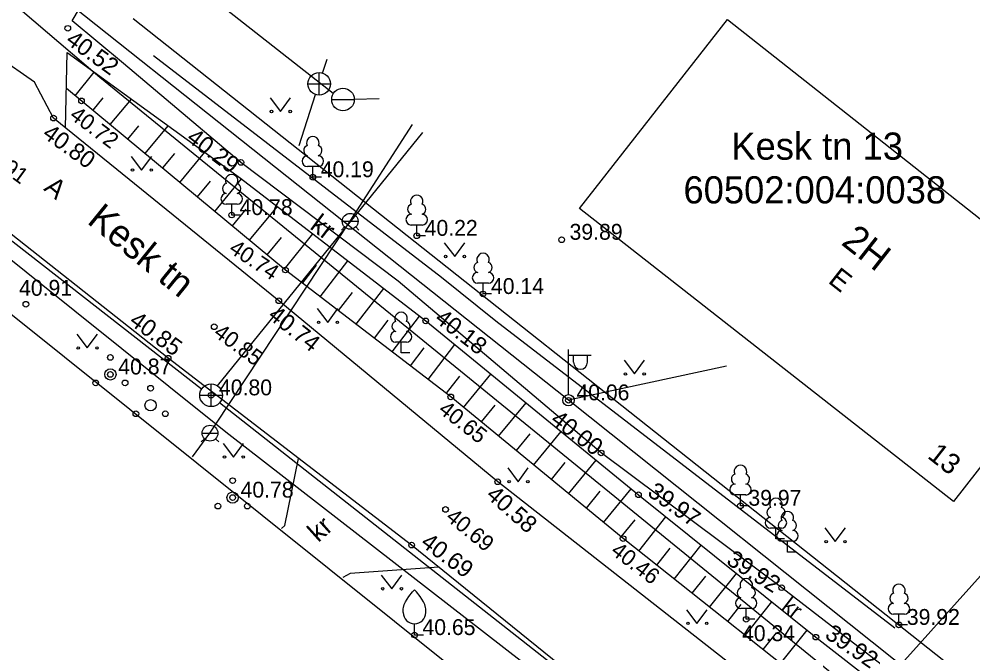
# Model space of a CAD drawing. Extents: x 641898 to 642452, y 6471715 to 6472255.
# Drawn here: x 642247.36 to 642289.49, y 6471869.14 to 6471897.14 of the extents above; entities that cross this region are included whole.
import ezdxf

# ---------------------------------------------------------------- set-up
doc = ezdxf.new("R2010")
doc.units = 0
for name, color, linetype in [('HALJASTUS', 7, 'Continuous'), ('HOONE', 7, 'Continuous'), ('KKAEV', 7, 'Continuous'), ('KORGUS-EH2000', 7, 'Continuous'), ('KTRASS', 7, 'Continuous'), ('MPOHULIIN', 7, 'Continuous'), ('PIIR', 7, 'Continuous'), ('POST', 7, 'Continuous'), ('PUU', 7, 'Continuous'), ('RELJEEF', 7, 'Continuous'), ('TEE', 7, 'Continuous'), ('VKAEV', 7, 'Continuous'), ('VTRASS', 7, 'Continuous')]:
    doc.layers.add(name, color=color, linetype=linetype)

msp = doc.modelspace()

# ---------------------------------------------------------------- linework, layer by layer
at = {"layer": 'HALJASTUS'}
for p, q in [((642258.446, 6471893.663), (642258.91, 6471893.056)), ((642258.91, 6471893.056), (642259.355, 6471893.663)), ((642252.309, 6471891.077), (642252.772, 6471890.47)), ((642252.772, 6471890.47), (642253.218, 6471891.077)), ((642266.14, 6471887.258), (642266.603, 6471886.651)), ((642266.603, 6471886.651), (642267.049, 6471887.258)), ((642260.531, 6471884.349), (642260.994, 6471883.742)), ((642260.994, 6471883.742), (642261.44, 6471884.349)), ((642249.91, 6471883.22), (642250.373, 6471882.613)), ((642250.373, 6471882.613), (642250.819, 6471883.22)), ((642274.083, 6471882.072), (642274.546, 6471881.465)), ((642274.546, 6471881.465), (642274.992, 6471882.072)), ((642256.37, 6471878.401), (642256.834, 6471877.794)), ((642256.834, 6471877.794), (642257.279, 6471878.401)), ((642268.944, 6471877.312), (642269.407, 6471876.705)), ((642269.407, 6471876.705), (642269.853, 6471877.312)), ((642282.951, 6471874.667), (642283.414, 6471874.061)), ((642283.414, 6471874.061), (642283.86, 6471874.667)), ((642263.359, 6471872.583), (642263.822, 6471871.977)), ((642263.822, 6471871.977), (642264.268, 6471872.583)), ((642276.843, 6471871.053), (642277.306, 6471870.447)), ((642277.306, 6471870.447), (642277.752, 6471871.053))]:
    msp.add_line(p, q, dxfattribs=at)
msp.add_lwpolyline([(642253.304, 6471895.534), (642266.025, 6471885.741), (642268.417, 6471883.816), (642286.045, 6471870.255)], dxfattribs=at)
for centre in [(642258.509, 6471893.056), (642259.337, 6471893.056), (642252.371, 6471890.47), (642253.2, 6471890.47), (642266.202, 6471886.651), (642267.031, 6471886.651), (642260.593, 6471883.742), (642261.422, 6471883.742), (642249.972, 6471882.613), (642250.801, 6471882.613), (642274.145, 6471881.465), (642274.974, 6471881.465), (642256.433, 6471877.794), (642257.261, 6471877.794), (642269.006, 6471876.705), (642269.835, 6471876.705), (642283.013, 6471874.061), (642283.842, 6471874.061), (642263.421, 6471871.977), (642264.25, 6471871.977), (642276.905, 6471870.447), (642277.734, 6471870.447)]:
    msp.add_circle(centre, 0.055, dxfattribs=at)
at = {"layer": 'HOONE'}
msp.add_lwpolyline([(642295.123, 6471884.142), (642288.643, 6471875.825), (642272.118, 6471888.773), (642278.654, 6471897.128), (642295.123, 6471884.142)], dxfattribs=at)
at = {"layer": 'KKAEV'}
for p, q in [((642260.614, 6471893.779), (642260.614, 6471894.779)), ((642260.114, 6471894.279), (642261.114, 6471894.279)), ((642255.841, 6471880.022), (642255.841, 6471881.022)), ((642255.341, 6471880.522), (642256.341, 6471880.522))]:
    msp.add_line(p, q, dxfattribs=at)
for centre in [(642260.614, 6471894.279), (642255.841, 6471880.522)]:
    msp.add_circle(centre, 0.5, dxfattribs=at)
at = {"layer": 'KORGUS-EH2000'}
for centre in [(642249.511, 6471896.733), (642250.117, 6471893.526), (642248.882, 6471892.766), (642257.161, 6471890.808), (642260.336, 6471890.156), (642256.752, 6471888.484), (642264.926, 6471887.567), (642271.328, 6471887.393), (642259.128, 6471886.055), (642267.855, 6471884.997), (642258.832, 6471884.697), (642255.978, 6471883.551), (642265.322, 6471883.81), (642253.944, 6471882.162), (642251.393, 6471881.444), (642255.841, 6471880.522), (642266.428, 6471880.453), (642271.629, 6471880.301), (642273.071, 6471877.975), (642268.501, 6471876.701), (642256.794, 6471876.004), (642274.72, 6471876.131), (642266.199, 6471875.479), (642279.226, 6471875.645), (642274.043, 6471874.191), (642264.701, 6471873.908), (642281.048, 6471872.025), (642279.481, 6471870.628), (642286.226, 6471870.383), (642264.829, 6471869.934), (642282.556, 6471869.84)]:
    msp.add_circle(centre, 0.125, dxfattribs=at)
at = {"layer": 'KTRASS'}
for points in [[(642255.424, 6471880.798), (642227.22, 6471902.81)], [(642260.769, 6471894.754), (642260.971, 6471895.375)], [(642259.734, 6471891.562), (642260.46, 6471893.803)], [(642265.186, 6471892.134), (642256.105, 6471880.947)], [(642294.047, 6471850.472), (642256.209, 6471880.184)]]:
    msp.add_lwpolyline(points, dxfattribs=at)
at = {"layer": 'MPOHULIIN'}
for points in [[(642355.522, 6471813.313), (642331.534, 6471832.393), (642302.222, 6471855.921), (642271.629, 6471880.301), (642234.793, 6471909.555), (642198.436, 6471939.015), (642169.975, 6471961.956), (642133.076, 6471995.171), (642102.99, 6472021.089), (642074.552, 6472045.947), (642044.597, 6472041.824), (642019.939, 6472060.923), (641980.015, 6472091.706), (641945.513, 6472065.466), (641932.178, 6472056.628)], [(642278.615, 6471881.808), (642271.629, 6471880.301)]]:
    msp.add_lwpolyline(points, dxfattribs=at)
at = {"layer": 'PIIR'}
for p, q in [((642186.7, 6471949.52), (642250.92, 6471894.58)), ((642228.06, 6471899.25), (642288.16, 6471851.19)), ((642289.81, 6471867.53), (642252.4, 6471897.15)), ((642250.92, 6471894.58), (642294.31, 6471859.27))]:
    msp.add_line(p, q, dxfattribs=at)
at = {"layer": 'POST'}
for p, q in [((642271.629, 6471880.551), (642271.629, 6471882.551)), ((642271.629, 6471882.301), (642272.629, 6471882.301)), ((642271.856, 6471881.98), (642271.856, 6471882.301)), ((642272.468, 6471881.98), (642272.468, 6471882.301))]:
    msp.add_line(p, q, dxfattribs=at)
msp.add_circle((642271.629, 6471880.301), 0.25, dxfattribs=at)
msp.add_arc((642272.162, 6471881.98), 0.306, 180, 0, dxfattribs=at)
at = {"layer": 'PUU'}
for p, q in [((642260.576, 6471890.631), (642260.096, 6471890.631)), ((642260.336, 6471890.156), (642260.336, 6471890.631)), ((642260.716, 6471890.156), (642260.336, 6471890.156)), ((642256.992, 6471888.959), (642256.512, 6471888.959)), ((642256.752, 6471888.484), (642256.752, 6471888.959)), ((642257.132, 6471888.484), (642256.752, 6471888.484)), ((642265.166, 6471888.042), (642264.686, 6471888.042)), ((642264.926, 6471887.567), (642264.926, 6471888.042)), ((642265.306, 6471887.567), (642264.926, 6471887.567)), ((642268.095, 6471885.472), (642267.615, 6471885.472)), ((642267.855, 6471884.997), (642267.855, 6471885.472)), ((642268.235, 6471884.997), (642267.855, 6471884.997)), ((642264.475, 6471882.868), (642263.995, 6471882.868)), ((642264.235, 6471882.393), (642264.235, 6471882.868)), ((642264.615, 6471882.393), (642264.235, 6471882.393)), ((642279.466, 6471876.12), (642278.986, 6471876.12)), ((642279.226, 6471875.645), (642279.226, 6471876.12)), ((642279.606, 6471875.645), (642279.226, 6471875.645)), ((642281.033, 6471874.652), (642280.553, 6471874.652)), ((642280.793, 6471874.177), (642280.793, 6471874.652)), ((642281.173, 6471874.177), (642280.793, 6471874.177)), ((642281.54, 6471874.075), (642281.06, 6471874.075)), ((642281.3, 6471873.6), (642281.3, 6471874.075)), ((642281.68, 6471873.6), (642281.3, 6471873.6)), ((642279.721, 6471871.103), (642279.241, 6471871.103)), ((642279.481, 6471870.628), (642279.481, 6471871.103)), ((642279.861, 6471870.628), (642279.481, 6471870.628)), ((642286.466, 6471870.858), (642285.986, 6471870.858)), ((642286.226, 6471870.383), (642286.226, 6471870.858)), ((642264.829, 6471869.934), (642264.829, 6471870.434)), ((642286.606, 6471870.383), (642286.226, 6471870.383)), ((642265.229, 6471869.934), (642264.829, 6471869.934))]:
    msp.add_line(p, q, dxfattribs=at)
for points in [[(642264.329, 6471870.934), (642264.329, 6471871.084), (642264.339, 6471871.149), (642264.374, 6471871.279), (642264.434, 6471871.399), (642264.579, 6471871.634), (642264.739, 6471871.839), (642264.829, 6471871.934)], [(642265.329, 6471870.934), (642265.329, 6471871.084), (642265.319, 6471871.149), (642265.284, 6471871.279), (642265.224, 6471871.399), (642265.079, 6471871.634), (642264.919, 6471871.839), (642264.829, 6471871.934)]]:
    msp.add_lwpolyline(points, dxfattribs=at)
for centre, radius in [((642247.659, 6471884.544), 0.125), ((642251.393, 6471882.194), 0.125), ((642251.393, 6471881.444), 0.25), ((642250.743, 6471881.069), 0.125), ((642252.043, 6471881.069), 0.125), ((642253.169, 6471880.833), 0.125), ((642253.169, 6471880.083), 0.25), ((642252.519, 6471879.708), 0.125), ((642253.819, 6471879.708), 0.125), ((642256.794, 6471876.754), 0.125), ((642256.794, 6471876.004), 0.25), ((642256.144, 6471875.629), 0.125), ((642257.444, 6471875.629), 0.125)]:
    msp.add_circle(centre, radius, dxfattribs=at)
for centre, radius, start, end in [((642260.336, 6471891.676), 0.277, 332.5799, 207.4201), ((642260.166, 6471891.329), 0.233, 109.0217, 253.1415), ((642260.506, 6471891.329), 0.233, 286.8508, 70.9859), ((642260.099, 6471890.868), 0.238, 90.0016, 269.3953), ((642260.573, 6471890.868), 0.238, 270.6047, 89.9984), ((642256.752, 6471890.004), 0.277, 332.5799, 207.4201), ((642256.582, 6471889.657), 0.233, 109.0217, 253.1415), ((642256.922, 6471889.657), 0.233, 286.8508, 70.9859), ((642256.515, 6471889.196), 0.238, 90.0016, 269.3953), ((642256.989, 6471889.196), 0.238, 270.6047, 89.9984), ((642264.926, 6471889.087), 0.277, 332.5799, 207.4201), ((642264.756, 6471888.74), 0.233, 109.0217, 253.1415), ((642265.096, 6471888.74), 0.233, 286.8508, 70.9859), ((642264.689, 6471888.279), 0.238, 90.0016, 269.3953), ((642265.163, 6471888.279), 0.238, 270.6047, 89.9984), ((642267.855, 6471886.517), 0.277, 332.5799, 207.4201), ((642267.685, 6471886.17), 0.233, 109.0217, 253.1415), ((642268.025, 6471886.17), 0.233, 286.8508, 70.9859), ((642267.618, 6471885.709), 0.238, 90.0016, 269.3953), ((642268.092, 6471885.709), 0.238, 270.6047, 89.9984), ((642264.235, 6471883.913), 0.277, 332.5799, 207.4201), ((642264.065, 6471883.566), 0.233, 109.0217, 253.1415), ((642264.405, 6471883.566), 0.233, 286.8508, 70.9859), ((642263.998, 6471883.105), 0.238, 90.0016, 269.3953), ((642264.472, 6471883.105), 0.238, 270.6047, 89.9984), ((642279.226, 6471877.165), 0.277, 332.5799, 207.4201), ((642279.056, 6471876.818), 0.233, 109.0217, 253.1415), ((642279.396, 6471876.818), 0.233, 286.8508, 70.9859), ((642278.989, 6471876.357), 0.238, 90.0016, 269.3953), ((642279.463, 6471876.357), 0.238, 270.6047, 89.9984), ((642280.623, 6471875.35), 0.233, 109.0217, 253.1415), ((642280.793, 6471875.697), 0.277, 332.5799, 207.4201), ((642280.963, 6471875.35), 0.233, 286.8508, 70.9859), ((642281.3, 6471875.12), 0.277, 332.5799, 207.4201), ((642280.556, 6471874.889), 0.238, 90.0016, 269.3953), ((642281.13, 6471874.773), 0.233, 109.0217, 253.1415), ((642281.03, 6471874.889), 0.238, 270.6047, 89.9984), ((642281.47, 6471874.773), 0.233, 286.8508, 70.9859), ((642281.063, 6471874.312), 0.238, 90.0016, 269.3953), ((642281.537, 6471874.312), 0.238, 270.6047, 89.9984), ((642279.481, 6471872.148), 0.277, 332.5799, 207.4201), ((642279.311, 6471871.801), 0.233, 109.0217, 253.1415), ((642279.651, 6471871.801), 0.233, 286.8508, 70.9859), ((642286.056, 6471871.556), 0.233, 109.0217, 253.1415), ((642286.226, 6471871.903), 0.277, 332.5799, 207.4201), ((642286.396, 6471871.556), 0.233, 286.8508, 70.9859), ((642279.244, 6471871.34), 0.238, 90.0016, 269.3953), ((642279.718, 6471871.34), 0.238, 270.6047, 89.9984), ((642264.829, 6471870.934), 0.5, 180, 0), ((642285.989, 6471871.095), 0.238, 90.0016, 269.3953), ((642286.463, 6471871.095), 0.238, 270.6047, 89.9984)]:
    msp.add_arc(centre, radius, start, end, dxfattribs=at)
at = {"layer": 'RELJEEF'}
for p, q in [((642249.843, 6471893.753), (642250.672, 6471894.8)), ((642251.061, 6471893.654), (642250.613, 6471893.115)), ((642251.383, 6471892.476), (642252.32, 6471893.606)), ((642252.642, 6471892.428), (642252.153, 6471891.838)), ((642252.923, 6471891.2), (642253.943, 6471892.43)), ((642254.224, 6471891.202), (642253.693, 6471890.562)), ((642254.462, 6471889.923), (642255.566, 6471891.254)), ((642255.805, 6471889.976), (642255.232, 6471889.285)), ((642256.002, 6471888.647), (642257.188, 6471890.077)), ((642257.376, 6471888.737), (642256.772, 6471888.009)), ((642257.542, 6471887.37), (642258.773, 6471888.856)), ((642258.939, 6471887.488), (642258.311, 6471886.732)), ((642259.081, 6471886.094), (642260.33, 6471887.656)), ((642260.483, 6471886.276), (642259.873, 6471885.483)), ((642260.667, 6471884.874), (642261.883, 6471886.46)), ((642262.068, 6471885.057), (642261.46, 6471884.266)), ((642262.253, 6471883.657), (642263.467, 6471885.239)), ((642263.84, 6471882.439), (642265.052, 6471884.018)), ((642263.653, 6471883.838), (642263.046, 6471883.048)), ((642265.426, 6471881.222), (642266.607, 6471882.76)), ((642265.233, 6471882.612), (642264.633, 6471881.83)), ((642266.998, 6471879.985), (642268.199, 6471881.459)), ((642266.81, 6471881.362), (642266.22, 6471880.613)), ((642268.375, 6471880.085), (642267.77, 6471879.349)), ((642268.542, 6471878.714), (642269.755, 6471880.188)), ((642269.922, 6471878.817), (642269.315, 6471878.079)), ((642270.087, 6471877.444), (642271.303, 6471878.923)), ((642271.469, 6471877.549), (642270.86, 6471876.809)), ((642271.632, 6471876.174), (642272.852, 6471877.657)), ((642273.015, 6471876.282), (642272.404, 6471875.538)), ((642273.177, 6471874.903), (642274.401, 6471876.392)), ((642274.731, 6471873.645), (642275.933, 6471875.157)), ((642274.558, 6471875.02), (642273.949, 6471874.268)), ((642276.298, 6471872.402), (642277.491, 6471873.906)), ((642276.113, 6471873.778), (642275.515, 6471873.024)), ((642277.865, 6471871.159), (642279.051, 6471872.654)), ((642277.676, 6471872.53), (642277.082, 6471871.781)), ((642279.432, 6471869.916), (642280.61, 6471871.402)), ((642279.24, 6471871.283), (642278.649, 6471870.538)), ((642280.999, 6471868.674), (642282.17, 6471870.15)), ((642280.803, 6471870.036), (642280.216, 6471869.295))]:
    msp.add_line(p, q, dxfattribs=at)
msp.add_lwpolyline([(642284.133, 6471866.188), (642274.043, 6471874.191), (642266.428, 6471880.453), (642259.128, 6471886.055), (642249.449, 6471894.08)], dxfattribs=at)
at = {"layer": 'TEE'}
for points in [[(642291.124, 6471873.995), (642285.962, 6471868.23), (642281.048, 6471872.025), (642273.071, 6471877.975), (642264.111, 6471885.566), (642257.161, 6471890.808), (642251.979, 6471895.17), (642249.705, 6471897.061), (642252.54, 6471901.858)], [(642294.249, 6471856.362), (642285.195, 6471863.473), (642284.274, 6471864.186), (642278.847, 6471868.608), (642268.501, 6471876.701), (642258.832, 6471884.697), (642248.882, 6471892.766), (642248.038, 6471894.359), (642244.819, 6471896.591)], [(642249.408, 6471892.339), (642249.486, 6471895.66), (642257.144, 6471890.111), (642265.322, 6471883.81), (642274.72, 6471876.131), (642282.556, 6471869.84), (642285.419, 6471867.624), (642283.156, 6471865.097)], [(642366.559, 6471781.691), (642366.75, 6471785.551), (642365.695, 6471788.509), (642364.88, 6471791.554), (642359.32, 6471797.565), (642349.55, 6471805.814), (642345.029, 6471809.364), (642338.375, 6471814.612), (642330.338, 6471821.174), (642323.486, 6471826.682), (642313.328, 6471834.865), (642303.076, 6471843.066), (642293.352, 6471850.788), (642283.707, 6471858.589), (642276.578, 6471864.269), (642271.231, 6471868.612), (642264.701, 6471873.908), (642253.944, 6471882.162), (642243.566, 6471890.342)], [(642258.956, 6471874.644), (642259.093, 6471874.767), (642259.709, 6471877.738)], [(642265.897, 6471872.938), (642261.983, 6471872.648), (642261.658, 6471872.476)]]:
    msp.add_lwpolyline(points, dxfattribs=at)
at = {"layer": 'VKAEV'}
for p, q in [((642261.168, 6471893.589), (642262.168, 6471893.589)), ((642261.638, 6471888.208), (642262.338, 6471888.208)), ((642261.741, 6471887.961), (642261.601, 6471887.821)), ((642262.235, 6471887.961), (642262.375, 6471887.821)), ((642255.545, 6471878.606), (642255.405, 6471878.466)), ((642255.442, 6471878.853), (642256.142, 6471878.853)), ((642256.039, 6471878.606), (642256.179, 6471878.466))]:
    msp.add_line(p, q, dxfattribs=at)
for centre, radius in [((642261.668, 6471893.589), 0.5), ((642261.988, 6471888.208), 0.35), ((642255.792, 6471878.853), 0.35)]:
    msp.add_circle(centre, radius, dxfattribs=at)
at = {"layer": 'VTRASS'}
for points in [[(642261.241, 6471893.85), (642226.798, 6471920.874), (642223.555, 6471923.471), (642220.019, 6471926.258), (642175.39, 6471960.391)], [(642263.264, 6471893.612), (642262.168, 6471893.589)], [(642256.057, 6471879.253), (642261.988, 6471888.208), (642264.74, 6471892.477)], [(642383.722, 6471805.593), (642379.745, 6471805.698), (642375.961, 6471804.651), (642372.001, 6471801.12), (642371.83, 6471800.837), (642365.292, 6471792.802), (642334.532, 6471817.276), (642325.31, 6471824.815), (642293.796, 6471849.944), (642275.212, 6471864.371), (642256.629, 6471878.798), (642256.057, 6471879.253), (642241.436, 6471890.95)], [(642255.015, 6471877.807), (642255.792, 6471878.853), (642256.057, 6471879.253)]]:
    msp.add_lwpolyline(points, dxfattribs=at)

# ---------------------------------------------------------------- texts
at = {"layer": 'HOONE'}
for s, height, p in [('2H', 1.2, (642283.632, 6471887.209)), ('E', 0.9, (642283.055, 6471885.52)), ('13', 0.9, (642287.444, 6471877.784))]:
    msp.add_text(s, height=height, rotation=321.9203, dxfattribs=at).set_placement(p)
at = {"layer": 'KORGUS-EH2000'}
for s, height, rotation, p in [('40.52', 0.75, 324.0197, (642249.374, 6471896.095)), ('40.72', 0.7, 323.0353, (642249.544, 6471892.787)), ('40.80', 0.75, 324.217, (642248.343, 6471891.96)), ('40.29', 0.75, 323.1469, (642254.709, 6471891.782)), ('40.91', 0.7, 323.8569, (642245.542, 6471891.199)), ('40.74', 0.7, 326.294, (642256.582, 6471886.87)), ('40.85', 0.75, 324.0059, (642252.18, 6471883.69)), ('40.74', 0.75, 321.4826, (642258.309, 6471883.958)), ('40.18', 0.75, 322.1639, (642265.672, 6471883.81)), ('40.85', 0.7, 323.3959, (642255.906, 6471883.178)), ('40.65', 0.7, 321.8067, (642265.838, 6471879.798)), ('40.00', 0.75, 322.7486, (642270.787, 6471879.335)), ('39.97', 0.75, 324.3187, (642275.07, 6471876.131)), ('40.58', 0.75, 318.5044, (642267.945, 6471876.046)), ('40.69', 0.7, 320.5316, (642266.162, 6471875.058)), ('40.69', 0.75, 323.3668, (642265.051, 6471873.908)), ('40.46', 0.7, 322.5266, (642273.453, 6471873.553)), ('39.92', 0.75, 327.9664, (642278.559, 6471873.097)), ('39.92', 0.75, 325.6036, (642282.906, 6471869.84))]:
    msp.add_text(s, height=height, rotation=rotation, dxfattribs=at).set_placement(p)
for s, p in [('40.19', (642260.686, 6471890.156)), ('40.78', (642257.102, 6471888.484)), ('40.22', (642265.276, 6471887.567)), ('39.89', (642271.678, 6471887.393)), ('40.14', (642268.205, 6471884.997)), ('40.91', (642247.359, 6471884.919)), ('40.87', (642251.743, 6471881.444)), ('40.80', (642256.191, 6471880.522)), ('40.06', (642271.979, 6471880.301)), ('40.78', (642257.144, 6471876.004)), ('39.97', (642279.576, 6471875.645)), ('39.92', (642286.576, 6471870.383)), ('40.65', (642265.179, 6471869.934)), ('40.34', (642279.295, 6471869.665))]:
    msp.add_text(s, height=0.7, dxfattribs=at).set_placement(p)
at = {"layer": 'PIIR'}
for s, p in [('Kesk tn 13', (642278.823, 6471890.928)), ('60502:004:0038', (642276.708, 6471888.997))]:
    msp.add_text(s, height=1.2, dxfattribs=at).set_placement(p)
at = {"layer": 'TEE'}
for s, height, rotation, p in [('A', 0.85, 320.9595, (642248.41, 6471889.606)), ('Kesk tn', 1.2, 320.9595, (642250.316, 6471888.153)), ('kr', 0.85, 322.9748, (642260.162, 6471887.907)), ('kr', 0.85, 42.0242, (642260.577, 6471873.994)), ('kr', 0.7, 322.3245, (642281.001, 6471871.104))]:
    msp.add_text(s, height=height, rotation=rotation, dxfattribs=at).set_placement(p)

doc.saveas('drawing.dxf')
